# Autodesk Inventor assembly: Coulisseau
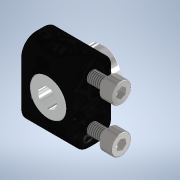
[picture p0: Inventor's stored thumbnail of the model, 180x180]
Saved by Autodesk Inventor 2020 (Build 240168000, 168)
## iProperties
Created: 2023-10
Part Number: Coulisseau
Document SubType Name: Assembly
Designer: bruno
Author: bruno
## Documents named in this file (4)
- C:\Users\bruno\Documents\1-Cours-2023-24\Maquettes-Inventor\Pince-robot-Dobot\Coulisseau.iam
- C:\Users\bruno\Documents\1-Cours-2023-24\Maquettes-Inventor\Pince-robot-Dobot\Support-bielles.ipt
- C:\Users\bruno\Documents\1-Cours-2023-24\Maquettes-Inventor\Pince-robot-Dobot\Douille.ipt
- C:\Users\bruno\Documents\Inventor\Content Center Files\R2020\fr-FR\KS B 1003\KS B 1003 - M 3 x 10.ipt
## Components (4 placed, 3 different names)
1. Support-bielles:1 — Placage:1, Affleurement:1, Placage:2, Placage:3, Placage:4, Placage:5
2. Douille:1 — Placage:1, Affleurement:1
3. KS B 1003 - Métrique M 3 x 10:1 — Placage:2, Placage:5
4. KS B 1003 - Métrique M 3 x 10:2 — Placage:3, Placage:4
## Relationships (6: Mate 5, Flush 1)
- Placage:1 [Mate]: Support-bielles:1 ↔ Douille:1
- Affleurement:1 [Flush]: Support-bielles:1 ↔ Douille:1
- Placage:2 [Mate]: Support-bielles:1 ↔ KS B 1003 - Métrique M 3 x 10:1
- Placage:3 [Mate]: Support-bielles:1 ↔ KS B 1003 - Métrique M 3 x 10:2
- Placage:4 [Mate]: Support-bielles:1 ↔ KS B 1003 - Métrique M 3 x 10:2
- Placage:5 [Mate]: Support-bielles:1 ↔ KS B 1003 - Métrique M 3 x 10:1
